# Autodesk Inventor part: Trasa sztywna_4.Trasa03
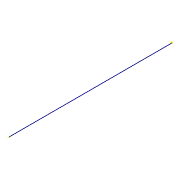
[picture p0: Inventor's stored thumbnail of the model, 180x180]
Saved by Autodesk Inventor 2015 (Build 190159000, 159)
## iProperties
Created: 2014-08
Part Number: Trasa sztywna_4.Trasa03
Material: Ogólny
Document SubType Name: Modeling
Designer: F.Stasiak
Density: 1 g/cm^3
Appearance: Domyślna
Catalog Web Link: www.expertbooks.pl
StyleName: _Piping Style 52
Manager: www.cadconsulting.pl
Company: Fabian Stasiak CAD Consulting
_PSKETCH_SNAP: False
_PSKETCH_RSNP: False
_BASENETWORK_NOTAUTODIMENSION: False
Name: JIS G 3458/JIS B 2316 - Rury stalowe spawane i łączniki
ActiveState: True
PipeType: Rigid Pipe
Material: UnInitValue
Standard: UnInitValue
FittingMaterial: UnInitValue
FittingStandard: UnInitValue
RouteDirection90: True
RouteDirection45: True
IsFlanged: False
IsButtWelded: False
DiameterType: Nominal
Diameter: M40
Schedule: 80
OD: UnInitValue
ID: UnInitValue
Ending: UnInitValue
IntermediateSegmentsMin: 60,000 mm
IntermediateSegmentsMax: 5000,000 mm
IntermediateSegmentsInc: 1,000 mm
TerminationSegmentsMin: 60,000 mm
TerminationSegmentsMax: 5000,000 mm
TerminationSegmentsInc: 1,000 mm
RoundUpValue: UnInitValue
PipingComponentColor: As Material
PipeKey: v3#da14b0ab-0b36-4851-8d66-8c9cd0bcbe86#23
CouplingKey: v3#12b64993-10e6-4915-8315-0c0cce209ad0#8
Elbow90Key: v3#1f65ece3-c41a-48d4-8661-909ed34ade86#8
Elbow45Key: v3#28e76e79-e22c-40ab-8be2-ff545b1407c5#8
GasketKey: UnInitValue
FlangeKey: UnInitValue
_ComponentInfo: <CS><C N="Pipe" R="2.430000" IR="1.920000" PL="PL" PN="JIS G 3458 Pipe 40 A x Sch 80"><CO N="1"><FE V="0"/><FD V="1"/><ET V="Welded"/><NS V="M40"/><MA V="0.0000
Gap: UnInitValue
ShowGap: UnInitValue
MixedUnits: False
UseFlangsForCouplings: UnInitValue
IsSelfDraining: False
ElbowCustomKey: UnInitValue
Author: F.Stasiak
Subject: Zbiór ćwiczeń. Autodesk Inventor 2020. Kurs Professional
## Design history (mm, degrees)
node "Punkt konstrukcyjny1"
node "Punkt konstrukcyjny2"
sketch "Szkic 3D1"
